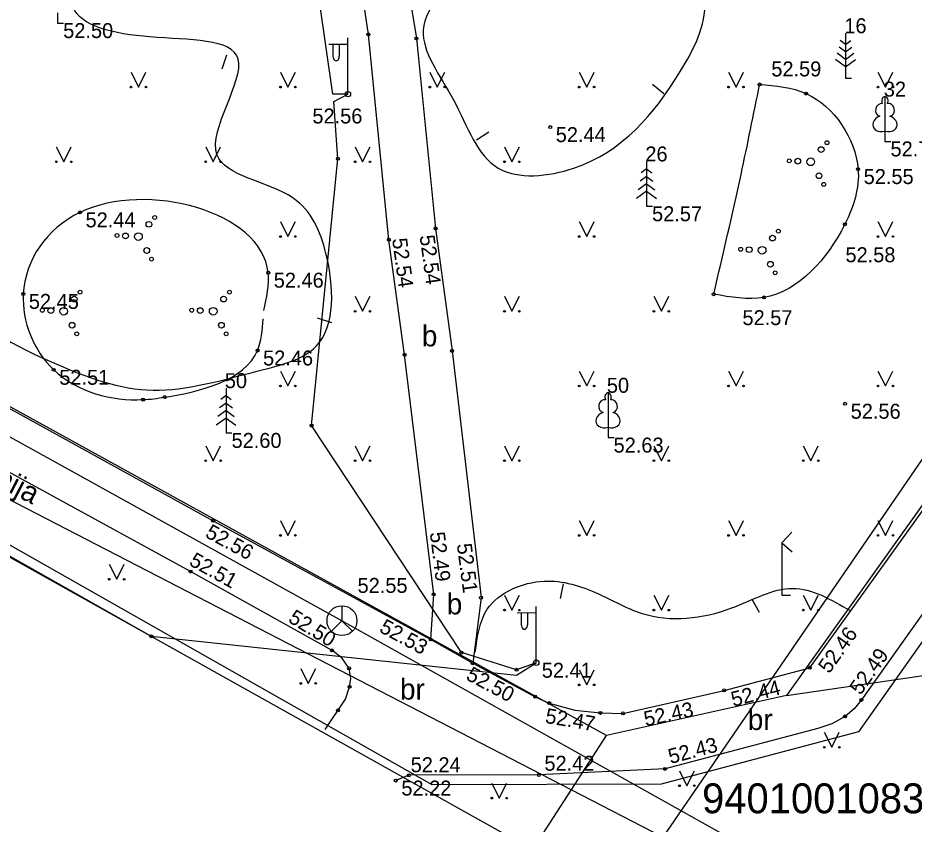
# Model space of a CAD drawing. Extents: x 619806 to 620082, y 405176 to 405386.
# Drawn here: x 619968.46 to 619998.46, y 405197.84 to 405224.81 of the extents above; entities that cross this region are included whole.
import ezdxf

# ---------------------------------------------------------------- set-up
doc = ezdxf.new("R2010")
doc.units = 0
for name, color, linetype in [('APGR_SARK_####_####_#', 7, 'Continuous'), ('APGR_SARK_IZNL_TKST_#', 7, 'Continuous'), ('APGS_ELEM_####_####_#', 7, 'Continuous'), ('APGS_VADP_ZSPR_####_#', 7, 'Continuous'), ('CELI_CMAL_####_####_#', 7, 'Continuous'), ('CELI_CSEG_####_TKST_#', 7, 'Continuous'), ('CELI_ELEM_####_####_#', 7, 'Continuous'), ('CELI_SEGL_####_####_#', 7, 'Continuous'), ('RAMI_UZMR_####_####_#', 7, 'Continuous'), ('RELJ_AATZ_####_TKST_#', 7, 'Continuous'), ('RELJ_ELEM_####_####_#', 7, 'Continuous'), ('RELJ_HORZ_PAMT_####_#', 7, 'Continuous'), ('ROBZ_PROJ_####_####_#', 7, 'Continuous'), ('ROBZ_PROJ_####_TKST_#', 7, 'Continuous'), ('ROBZ_UZMR_####_####_#', 7, 'Continuous'), ('SAKK_ELEM_####_####_#', 7, 'Continuous'), ('SAKK_ELEM_####_TKST_#', 7, 'Continuous'), ('SAKK_KKAN_####_####_#', 7, 'Continuous'), ('SAKT_VADP_KABE_####_#', 7, 'Continuous'), ('TERT_DIAM_####_TKST_#', 7, 'Continuous'), ('TERT_ELEM_####_####_#', 7, 'Continuous'), ('TERT_KONT_####_####_#', 7, 'Continuous')]:
    doc.layers.add(name, color=color, linetype=linetype)

msp = doc.modelspace()

# ---------------------------------------------------------------- linework, layer by layer
at = {"layer": 'APGR_SARK_####_####_#'}
for points in [[(619976.198, 405343.424), (619987.786, 405326.116), (620001.138, 405307.928), (620014.265, 405290.061), (620015.405, 405288.784), (620016.767, 405287.746), (620041.487, 405272.379), (619990.053, 405197.403), (619990.053, 405197.403)], [(619990.053, 405197.403), (619966.019, 405209.806), (619941.986, 405222.21), (619880.273, 405256.839), (619818.56, 405291.467)]]:
    msp.add_lwpolyline(points, dxfattribs=at)
at = {"layer": 'APGS_ELEM_####_####_#'}
for p, q in [((619979.51, 405222.264), (619979.51, 405224.147)), ((619979.51, 405223.931), (619978.875, 405223.926)), ((619979.01, 405223.927), (619979.01, 405223.535)), ((619979.22, 405223.929), (619979.22, 405223.535)), ((619985.811, 405203.238), (619985.811, 405205.121)), ((619985.811, 405204.905), (619985.176, 405204.9)), ((619985.311, 405204.901), (619985.311, 405204.509)), ((619985.521, 405204.903), (619985.521, 405204.509))]:
    msp.add_line(p, q, dxfattribs=at)
for centre in [(619979.51, 405222.264), (619985.811, 405203.238)]:
    msp.add_circle(centre, 0.09, dxfattribs=at)
for centre in [(619979.115, 405223.535), (619985.416, 405204.509)]:
    msp.add_ellipse(centre, major_axis=(0, 0.151), ratio=0.695971, start_param=1.570796, end_param=4.712389, dxfattribs=at)
at = {"layer": 'APGS_VADP_ZSPR_####_#'}
msp.add_lwpolyline([(619938.618, 405223.547), (619972.929, 405204.127), (619985.155, 405202.826), (619985.811, 405203.238), (619985.154, 405203.005), (619983.308, 405203.577), (619978.291, 405211.172), (619979.175, 405220.104), (619979.035, 405222.014), (619979.51, 405222.264), (619979.008, 405222.268), (619977.44, 405233.124), (619976.223, 405241.622), (619977.344, 405241.94), (619976.176, 405241.874), (619974.789, 405253.607), (619974.705, 405261.349), (619975.127, 405262.48)], dxfattribs=at)
at = {"layer": 'CELI_CMAL_####_####_#'}
for points in [[(619982.283, 405204.018), (619982.381, 405205.526), (619981.404, 405213.543), (619980.879, 405217.395), (619980.193, 405224.262), (619979.707, 405227.554), (619978.646, 405227.479), (619978.06, 405232.469), (619979.052, 405232.579), (619978.008, 405242.924), (619976.591, 405255.672), (619975.781, 405263.512), (619969.844, 405259.482), (619963.066, 405254.752), (619955.624, 405249.587), (619947.422, 405243.791), (619942.081, 405239.98), (619941.835, 405240.299), (619936.133, 405229.455), (619943.441, 405225.387), (619954.092, 405219.528), (619965.106, 405213.442), (619974.994, 405207.99), (619982.283, 405204.018)], [(619978.832, 405249.941), (619981.369, 405226.774), (619981.804, 405224.124), (619982.441, 405217.773), (619982.996, 405213.675), (619983.965, 405205.418), (619983.685, 405203.225), (619985.778, 405202.103), (619986.248, 405201.889), (619987.106, 405201.651), (619987.96, 405201.56), (619988.713, 405201.545), (619992.1, 405202.316), (619994.967, 405203.071), (620002.119, 405213.03), (620010.184, 405224.469), (620017.253, 405234.372), (620024.304, 405244.304)], [(619978.752, 405201.011), (619979.424, 405202.021), (619979.564, 405202.436), (619979.607, 405202.714), (619979.55, 405203.052), (619979.303, 405203.399), (619978.982, 405203.652), (619974.243, 405206.289), (619963.757, 405212.03), (619953.443, 405217.716), (619942.194, 405223.883), (619933.774, 405228.562), (619924.371, 405233.711), (619924.04, 405233.797), (619923.689, 405233.804), (619923.346, 405233.679), (619923.051, 405233.473), (619922.837, 405233.256), (619922.669, 405233.014)], [(620011.952, 405221.698), (620011.164, 405222.283), (620004.158, 405212.507), (619996.695, 405201.997), (619996.454, 405201.7), (619996.147, 405201.443), (619995.7, 405201.193), (619995.235, 405201.037), (619990.124, 405199.688), (619985.9, 405199.485), (619981.548, 405199.473), (619981.112, 405199.297)]]:
    msp.add_lwpolyline(points, dxfattribs=at)
at = {"layer": 'CELI_ELEM_####_####_#'}
for points in [[(619994.369, 405207.607), (619994.027, 405207.251), (619994.383, 405206.952)], [(619994.027, 405207.251), (619994.027, 405205.499), (619994.326, 405205.499)]]:
    msp.add_lwpolyline(points, dxfattribs=at)
at = {"layer": 'CELI_SEGL_####_####_#'}
msp.add_lwpolyline([(619982.283, 405204.018), (619983.685, 405203.225)], dxfattribs=at)
at = {"layer": 'RAMI_UZMR_####_####_#'}
msp.add_lwpolyline([(619874.687, 405324.979), (619926.719, 405349.544), (619966.669, 405369.042), (620021.738, 405292.03), (620049.703, 405275.476), (620026.189, 405242.287), (620012.147, 405222.917), (619996.603, 405200.928), (619989.997, 405199.173), (619982.328, 405199.155), (619922.669, 405233.014), (619882.137, 405255.756), (619859.084, 405268.056), (619820.646, 405290.715), (619813.744, 405295.206), (619820.645, 405298.752)], close=True, dxfattribs=at)
at = {"layer": 'RELJ_ELEM_####_####_#'}
for centre in [(619980.193, 405224.262), (619981.804, 405224.124), (619993.288, 405222.59), (619994.846, 405222.284), (619986.279, 405221.16), (619979.175, 405220.104), (619996.585, 405219.756), (619970.542, 405218.307), (619982.441, 405217.773), (619996.142, 405217.91), (619980.879, 405217.395), (619976.841, 405216.29), (619968.645, 405215.579), (619991.751, 405215.571), (619993.431, 405215.462), (619976.484, 405213.686), (619981.404, 405213.543), (619982.996, 405213.675), (619969.663, 405213.04), (619972.654, 405212.042), (619973.378, 405212.126), (619996.149, 405211.904), (619978.291, 405211.172), (619974.994, 405207.99), (619974.243, 405206.289), (619982.381, 405205.526), (619983.965, 405205.418), (619972.929, 405204.127), (619982.283, 405204.018), (619978.982, 405203.652), (619983.308, 405203.577), (619979.55, 405203.052), (619983.685, 405203.225), (619985.154, 405203.005), (619994.967, 405203.071), (619979.564, 405202.436), (619985.778, 405202.103), (619992.1, 405202.316), (619986.248, 405201.889), (619996.695, 405201.997), (619979.173, 405201.644), (619987.96, 405201.56), (619988.713, 405201.545), (619996.147, 405201.443), (619990.124, 405199.688), (619981.548, 405199.473), (619985.9, 405199.485), (619981.112, 405199.297)]:
    msp.add_circle(centre, 0.05, dxfattribs=at)
at = {"layer": 'RELJ_HORZ_PAMT_####_#'}
for p, q in [((619975.301, 405223.108), (619975.454, 405223.584)), ((619989.698, 405222.601), (619990.086, 405222.286)), ((619984.231, 405220.996), (619983.811, 405220.725)), ((619978.483, 405214.781), (619978.959, 405214.629)), ((619986.625, 405205.392), (619986.724, 405205.882)), ((619993.286, 405204.916), (619993.044, 405205.353))]:
    msp.add_line(p, q, dxfattribs=at)
for points in [[(619952.192, 405242.46), (619958.269, 405245.178), (619960.212, 405247.147), (619962.71, 405245.388), (619969.834, 405240.326), (619973.191, 405239.787), (619973.537, 405236.062), (619972.621, 405231.011), (619971.007, 405227.497), (619970.308, 405225.195), (619972.877, 405224.18), (619975.834, 405223.443), (619975.125, 405220.25), (619977.669, 405218.792), (619978.775, 405216.928), (619978.459, 405213.841), (619976.501, 405213.003), (619972.992, 405212.359), (619969.535, 405213.328), (619966.616, 405215.931), (619967.251, 405218.057), (619966.078, 405220.067), (619963.269, 405223.678), (619959.906, 405226.02), (619956.916, 405226.372), (619951.315, 405227.272), (619948.301, 405227.78), (619946.134, 405229.326), (619943.292, 405232.49), (619942.821, 405234.331), (619944.296, 405235.783), (619946.209, 405238.021), (619948.046, 405239.888), (619950.691, 405241.967), (619952.192, 405242.46)], [(619984.185, 405227.378), (619985.762, 405228.802), (619988.112, 405228.802), (619990.713, 405227.124), (619991.454, 405225.372), (619990.633, 405223.024), (619987.075, 405219.79), (619984.539, 405219.79), (619983.041, 405222.072), (619982.032, 405224.412), (619983.558, 405226.687), (619984.185, 405227.378)], [(619983.772, 405203.593), (619984.175, 405205.03), (619986.073, 405205.969), (619987.871, 405205.552), (619989.353, 405204.888), (619992.356, 405205.072), (619994.392, 405205.729), (619996.32, 405204.985)]]:
    msp.add_spline(points, degree=3, dxfattribs=at)
at = {"layer": 'ROBZ_PROJ_####_####_#'}
for p, q in [((619994.191, 405202.148), (620003.548, 405203.517)), ((619983.776, 405194.044), (619988.165, 405200.806))]:
    msp.add_line(p, q, dxfattribs=at)
at = {"layer": 'ROBZ_UZMR_####_####_#'}
for p, q in [((620044.084, 405272.127), (619994.191, 405202.148)), ((619982.318, 405204.025), (619936.15, 405229.445)), ((619984.157, 405203.013), (619982.318, 405204.025)), ((619988.165, 405200.806), (619984.157, 405203.013)), ((619994.191, 405202.148), (619988.165, 405200.806))]:
    msp.add_line(p, q, dxfattribs=at)
at = {"layer": 'SAKK_ELEM_####_####_#'}
msp.add_line((619979.31, 405204.647), (619979.664, 405204.293), dxfattribs=at)
msp.add_lwpolyline([(619979.31, 405205.147), (619979.31, 405204.647), (619978.956, 405204.293)], dxfattribs=at)
msp.add_circle((619979.31, 405204.647), 0.5, dxfattribs=at)
at = {"layer": 'SAKK_KKAN_####_####_#'}
for p, q in [((619979.31, 405204.647), (619918.714, 405238.138)), ((619993.065, 405196.943), (619979.31, 405204.647))]:
    msp.add_line(p, q, dxfattribs=at)
at = {"layer": 'SAKT_VADP_KABE_####_#'}
msp.add_lwpolyline([(619817.668, 405301.762), (619818.308, 405291.251), (619820.058, 405288.244), (619821.78, 405286.435), (619865.996, 405262.382), (619894.538, 405246.913), (619928.954, 405228.717), (619988.18, 405195.595)], dxfattribs=at)
at = {"layer": 'TERT_ELEM_####_####_#'}
for p, q in [((619969.794, 405224.988), (619969.794, 405224.641)), ((619969.794, 405224.641), (619969.994, 405224.641)), ((619996.163, 405224.303), (619996.163, 405222.803)), ((619996.163, 405223.927), (619995.987, 405224.055)), ((619996.163, 405223.927), (619996.337, 405224.055)), ((619996.163, 405223.677), (619995.947, 405223.835)), ((619996.163, 405223.677), (619996.379, 405223.835)), ((619996.163, 405223.177), (619995.831, 405223.421)), ((619996.163, 405223.427), (619995.885, 405223.631)), ((619996.163, 405223.427), (619996.441, 405223.631)), ((619996.163, 405223.177), (619996.497, 405223.421)), ((619972.25, 405223), (619972.5, 405222.5)), ((619972.5, 405222.5), (619972.75, 405223)), ((619977.25, 405223), (619977.5, 405222.5)), ((619977.5, 405222.5), (619977.75, 405223)), ((619982.25, 405223), (619982.5, 405222.5)), ((619982.5, 405222.5), (619982.75, 405223)), ((619987.25, 405223), (619987.5, 405222.5)), ((619987.5, 405222.5), (619987.75, 405223)), ((619992.25, 405223), (619992.5, 405222.5)), ((619992.5, 405222.5), (619992.75, 405223)), ((619996.163, 405222.803), (619996.363, 405222.803)), ((619997.25, 405223), (619997.5, 405222.5)), ((619997.5, 405222.5), (619997.75, 405223)), ((619997.483, 405221.029), (619997.483, 405220.682)), ((619969.75, 405220.5), (619970, 405220)), ((619970, 405220), (619970.25, 405220.5)), ((619974.75, 405220.5), (619975, 405220)), ((619975, 405220), (619975.25, 405220.5)), ((619979.75, 405220.5), (619980, 405220)), ((619980, 405220), (619980.25, 405220.5)), ((619984.75, 405220.5), (619985, 405220)), ((619985, 405220), (619985.25, 405220.5)), ((619997.483, 405220.682), (619997.683, 405220.682)), ((619989.503, 405220.013), (619989.503, 405218.513)), ((619989.503, 405219.513), (619989.287, 405219.355)), ((619989.503, 405219.763), (619989.327, 405219.635)), ((619989.503, 405219.763), (619989.677, 405219.635)), ((619989.503, 405219.513), (619989.719, 405219.355)), ((619989.503, 405219.263), (619989.225, 405219.059)), ((619989.503, 405219.263), (619989.781, 405219.059)), ((619989.503, 405219.013), (619989.171, 405218.769)), ((619989.503, 405219.013), (619989.837, 405218.769)), ((619989.503, 405218.513), (619989.703, 405218.513)), ((619977.25, 405218), (619977.5, 405217.5)), ((619977.5, 405217.5), (619977.75, 405218)), ((619987.25, 405218), (619987.5, 405217.5)), ((619987.5, 405217.5), (619987.75, 405218)), ((619997.25, 405218), (619997.5, 405217.5)), ((619997.5, 405217.5), (619997.75, 405218)), ((619979.75, 405215.5), (619980, 405215)), ((619980, 405215), (619980.25, 405215.5)), ((619984.75, 405215.5), (619985, 405215)), ((619985, 405215), (619985.25, 405215.5)), ((619989.75, 405215.5), (619990, 405215)), ((619990, 405215), (619990.25, 405215.5)), ((619977.25, 405213), (619977.5, 405212.5)), ((619977.5, 405212.5), (619977.75, 405213)), ((619987.25, 405213), (619987.5, 405212.5)), ((619987.5, 405212.5), (619987.75, 405213)), ((619992.25, 405213), (619992.5, 405212.5)), ((619992.5, 405212.5), (619992.75, 405213)), ((619997.25, 405213), (619997.5, 405212.5)), ((619997.5, 405212.5), (619997.75, 405213)), ((619975.429, 405212.428), (619975.429, 405210.928)), ((619975.429, 405212.178), (619975.253, 405212.05)), ((619975.429, 405212.178), (619975.603, 405212.05)), ((619975.429, 405211.928), (619975.213, 405211.77)), ((619975.429, 405211.928), (619975.645, 405211.77)), ((619975.429, 405211.428), (619975.097, 405211.184)), ((619975.429, 405211.678), (619975.151, 405211.474)), ((619975.429, 405211.678), (619975.707, 405211.474)), ((619975.429, 405211.428), (619975.763, 405211.184)), ((619988.215, 405211.119), (619988.215, 405210.772)), ((619975.429, 405210.928), (619975.629, 405210.928)), ((619974.75, 405210.5), (619975, 405210)), ((619975, 405210), (619975.25, 405210.5)), ((619979.75, 405210.5), (619980, 405210)), ((619980, 405210), (619980.25, 405210.5)), ((619984.75, 405210.5), (619985, 405210)), ((619985, 405210), (619985.25, 405210.5)), ((619988.215, 405210.772), (619988.415, 405210.772)), ((619989.75, 405210.5), (619990, 405210)), ((619990, 405210), (619990.25, 405210.5)), ((619994.75, 405210.5), (619995, 405210)), ((619995, 405210), (619995.25, 405210.5)), ((619977.25, 405208), (619977.5, 405207.5)), ((619977.5, 405207.5), (619977.75, 405208)), ((619987.25, 405208), (619987.5, 405207.5)), ((619987.5, 405207.5), (619987.75, 405208)), ((619992.25, 405208), (619992.5, 405207.5)), ((619992.5, 405207.5), (619992.75, 405208)), ((619997.25, 405208), (619997.5, 405207.5)), ((619997.5, 405207.5), (619997.75, 405208)), ((619971.521, 405206.535), (619971.771, 405206.035)), ((619971.771, 405206.035), (619972.021, 405206.535)), ((619984.75, 405205.5), (619985, 405205)), ((619985, 405205), (619985.25, 405205.5)), ((619989.75, 405205.5), (619990, 405205)), ((619990, 405205), (619990.25, 405205.5)), ((619994.75, 405205.5), (619995, 405205)), ((619995, 405205), (619995.25, 405205.5)), ((619977.933, 405203.048), (619978.183, 405202.548)), ((619978.183, 405202.548), (619978.433, 405203.048)), ((619987.25, 405203), (619987.5, 405202.5)), ((619987.5, 405202.5), (619987.75, 405203)), ((619995.453, 405200.912), (619995.703, 405200.412)), ((619995.703, 405200.412), (619995.953, 405200.912)), ((619990.606, 405199.625), (619990.856, 405199.125)), ((619990.856, 405199.125), (619991.106, 405199.625)), ((619984.325, 405199.209), (619984.575, 405198.709)), ((619984.575, 405198.709), (619984.825, 405199.209))]:
    msp.add_line(p, q, dxfattribs=at)
for points in [[(619997.483, 405222.182), (619997.483, 405221.029)], [(619997.573, 405221.95), (619997.572, 405221.951)], [(619988.215, 405212.272), (619988.215, 405211.119)], [(619988.305, 405212.04), (619988.304, 405212.041)]]:
    msp.add_lwpolyline(points, dxfattribs=at)
for centre, radius in [((619972.25, 405222.5), 0.028), ((619972.75, 405222.5), 0.0263), ((619977.25, 405222.5), 0.028), ((619977.75, 405222.5), 0.0263), ((619982.25, 405222.5), 0.028), ((619982.75, 405222.5), 0.0263), ((619987.25, 405222.5), 0.028), ((619987.75, 405222.5), 0.0263), ((619992.25, 405222.5), 0.028), ((619992.75, 405222.5), 0.0263), ((619997.25, 405222.5), 0.028), ((619997.75, 405222.5), 0.0263), ((619995.544, 405220.639), 0.064), ((619995.348, 405220.408), 0.096), ((619994.282, 405220.034), 0.064), ((619994.566, 405220.021), 0.096), ((619995, 405220), 0.128), ((619969.75, 405220), 0.028), ((619970.25, 405220), 0.0263), ((619974.75, 405220), 0.028), ((619975.25, 405220), 0.0263), ((619979.75, 405220), 0.028), ((619980.25, 405220), 0.0263), ((619984.75, 405220), 0.028), ((619985.25, 405220), 0.0263), ((619995.276, 405219.533), 0.096), ((619995.434, 405219.244), 0.064), ((619972.848, 405217.908), 0.096), ((619973.044, 405218.139), 0.064), ((619993.917, 405217.679), 0.064), ((619971.782, 405217.534), 0.064), ((619972.066, 405217.521), 0.096), ((619972.5, 405217.5), 0.128), ((619977.25, 405217.5), 0.028), ((619977.75, 405217.5), 0.0263), ((619987.25, 405217.5), 0.028), ((619987.75, 405217.5), 0.0263), ((619993.72, 405217.447), 0.096), ((619997.25, 405217.5), 0.028), ((619997.75, 405217.5), 0.0263), ((619972.776, 405217.033), 0.096), ((619992.654, 405217.074), 0.064), ((619992.939, 405217.061), 0.096), ((619993.373, 405217.04), 0.128), ((619972.934, 405216.744), 0.064), ((619993.649, 405216.573), 0.096), ((619993.807, 405216.284), 0.064), ((619970.544, 405215.639), 0.064), ((619975.544, 405215.639), 0.064), ((619970.348, 405215.408), 0.096), ((619975.348, 405215.408), 0.096), ((619969.282, 405215.034), 0.064), ((619969.566, 405215.021), 0.096), ((619970, 405215), 0.128), ((619974.282, 405215.034), 0.064), ((619974.566, 405215.021), 0.096), ((619975, 405215), 0.128), ((619979.75, 405215), 0.028), ((619980.25, 405215), 0.0263), ((619984.75, 405215), 0.028), ((619985.25, 405215), 0.0263), ((619989.75, 405215), 0.028), ((619990.25, 405215), 0.0263), ((619970.276, 405214.533), 0.096), ((619975.276, 405214.533), 0.096), ((619970.434, 405214.244), 0.064), ((619975.434, 405214.244), 0.064), ((619977.25, 405212.5), 0.028), ((619977.75, 405212.5), 0.0263), ((619987.25, 405212.5), 0.028), ((619987.75, 405212.5), 0.0263), ((619992.25, 405212.5), 0.028), ((619992.75, 405212.5), 0.0263), ((619997.25, 405212.5), 0.028), ((619997.75, 405212.5), 0.0263), ((619974.75, 405210), 0.028), ((619975.25, 405210), 0.0263), ((619979.75, 405210), 0.028), ((619980.25, 405210), 0.0263), ((619984.75, 405210), 0.028), ((619985.25, 405210), 0.0263), ((619989.75, 405210), 0.028), ((619990.25, 405210), 0.0263), ((619994.75, 405210), 0.028), ((619995.25, 405210), 0.0263), ((619977.25, 405207.5), 0.028), ((619977.75, 405207.5), 0.0263), ((619987.25, 405207.5), 0.028), ((619987.75, 405207.5), 0.0263), ((619992.25, 405207.5), 0.028), ((619992.75, 405207.5), 0.0263), ((619997.25, 405207.5), 0.028), ((619997.75, 405207.5), 0.0263), ((619971.521, 405206.034), 0.028), ((619972.021, 405206.034), 0.0263), ((619984.75, 405205), 0.028), ((619985.25, 405205), 0.0263), ((619989.75, 405205), 0.028), ((619990.25, 405205), 0.0263), ((619994.75, 405205), 0.028), ((619995.25, 405205), 0.0263), ((619977.933, 405202.547), 0.028), ((619978.433, 405202.547), 0.0263), ((619987.25, 405202.5), 0.028), ((619987.75, 405202.5), 0.0263), ((619995.453, 405200.411), 0.028), ((619995.953, 405200.411), 0.0263), ((619990.606, 405199.124), 0.028), ((619991.106, 405199.124), 0.0263), ((619984.325, 405198.709), 0.028), ((619984.825, 405198.709), 0.0263)]:
    msp.add_circle(centre, radius, dxfattribs=at)
for centre, major_axis, ratio, start_param, end_param in [((619997.355, 405221.737), (-0.039, -0.212), 0.861323, 3.141593, 6.283185), ((619997.483, 405222.032), (0, -0.15), 0.707107, 3.14537, 5.287485), ((619997.483, 405222.032), (0, -0.15), 0.707107, 0.995701, 3.137816), ((619997.611, 405221.737), (0.039, -0.212), 0.861323, 0, 3.141593), ((619997.393, 405221.275), (0.307, 0.095), 0.814445, 1.570796, 4.752015), ((619997.573, 405221.275), (-0.307, 0.095), 0.814445, 1.531171, 4.712389), ((619988.087, 405211.827), (-0.039, -0.212), 0.861323, 3.141593, 6.283185), ((619988.215, 405212.122), (0, -0.15), 0.707107, 3.14537, 5.287485), ((619988.215, 405212.122), (0, -0.15), 0.707107, 0.995701, 3.137816), ((619988.343, 405211.827), (0.039, -0.212), 0.861323, 0, 3.141593), ((619988.125, 405211.365), (0.307, 0.095), 0.814445, 1.570796, 4.752015), ((619988.305, 405211.365), (-0.307, 0.095), 0.814445, 1.531171, 4.712389)]:
    msp.add_ellipse(centre, major_axis=major_axis, ratio=ratio, start_param=start_param, end_param=end_param, dxfattribs=at)
at = {"layer": 'TERT_KONT_####_####_#'}
for points in [[(619993.288, 405222.59), (619994.846, 405222.284), (619996.585, 405219.756), (619996.142, 405217.91), (619993.431, 405215.462), (619991.751, 405215.571)], [(619991.751, 405215.571), (619992.667, 405219.575), (619993.288, 405222.59)], [(619976.694, 405215.021), (619976.841, 405216.29), (619970.542, 405218.307), (619968.645, 405215.579), (619969.663, 405213.04), (619972.654, 405212.042), (619973.378, 405212.126), (619976.484, 405213.686), (619976.672, 405214.747)]]:
    msp.add_spline(points, degree=3, dxfattribs=at)

# ---------------------------------------------------------------- texts
at = {"layer": 'APGR_SARK_IZNL_TKST_#'}
msp.add_text('sark.līnija', height=0.7, rotation=332.7019, dxfattribs=at).set_placement((619965.441, 405210.341))
at = {"layer": 'CELI_CSEG_####_TKST_#'}
for s, p in [('b', (619981.984, 405213.825)), ('b', (619982.817, 405204.858)), ('br', (619981.252, 405202.006)), ('br', (619992.892, 405200.989))]:
    msp.add_text(s, height=0.7, dxfattribs=at).set_placement(p)
at = {"layer": 'RELJ_AATZ_####_TKST_#'}
for s, p in [(' 52.50', (619969.794, 405224.141)), (' 52.59', (619993.494, 405222.858)), (' 52.56', (619978.135, 405221.283)), (' 52.44', (619986.279, 405220.66)), (' 52.70', (619997.483, 405220.182)), (' 52.55', (619996.585, 405219.256)), (' 52.44', (619970.542, 405217.807)), (' 52.57', (619989.503, 405218.013)), (' 52.58', (619995.975, 405216.641)), (' 52.46', (619976.841, 405215.79)), (' 52.45', (619968.645, 405215.079)), (' 52.57', (619992.529, 405214.536)), (' 52.46', (619976.484, 405213.186)), (' 52.51', (619969.663, 405212.54)), (' 52.56', (619996.149, 405211.404)), (' 52.60', (619975.429, 405210.428)), (' 52.63', (619988.215, 405210.272)), (' 52.41', (619985.811, 405202.738)), (' 52.24', (619981.424, 405199.577)), (' 52.42', (619985.9, 405199.626)), (' 52.22', (619981.112, 405198.797))]:
    msp.add_text(s, height=0.5, dxfattribs=at).set_placement(p)
for s, rotation, p in [(' 52.54', 277.7612, (619980.962, 405217.602)), (' 52.54', 277.7128, (619981.882, 405217.706)), (' 52.56', 331.4127, (619974.538, 405207.551)), (' 52.49', 276.9743, (619982.228, 405207.776)), (' 52.51', 277.5079, (619983.127, 405207.388)), (' 52.51', 330.9064, (619974, 405206.613)), (' 52.50', 328.3305, (619977.322, 405204.723)), (' 52.53', 331.4765, (619980.365, 405204.379)), (' 52.46', 54.3162, (619995.506, 405202.698)), (' 52.49', 54.622, (619996.558, 405201.98)), (' 52.50', 331.8055, (619983.265, 405202.784)), (' 52.44', 14.7534, (619992.227, 405201.715)), (' 52.43', 11.8293, (619989.289, 405201.07)), (' 52.47', 350.159, (619985.905, 405201.264)), (' 52.43', 14.7855, (619990.126, 405199.802))]:
    msp.add_text(s, height=0.5, rotation=rotation, dxfattribs=at).set_placement(p)
at = {"layer": 'ROBZ_PROJ_####_TKST_#'}
msp.add_text('94010010837', height=1, dxfattribs=at).set_placement((619991.362, 405198.203))
at = {"layer": 'SAKK_ELEM_####_TKST_#'}
msp.add_text(' 52.55', height=0.5, dxfattribs=at).set_placement((619979.646, 405205.577))
at = {"layer": 'TERT_DIAM_####_TKST_#'}
for s, p in [(' 16', (619995.938, 405224.303)), (' 32', (619997.258, 405222.182)), (' 26', (619989.278, 405220.013)), (' 50', (619975.204, 405212.428)), (' 50', (619987.99, 405212.272))]:
    msp.add_text(s, height=0.5, dxfattribs=at).set_placement(p)

doc.saveas('drawing.dxf')
